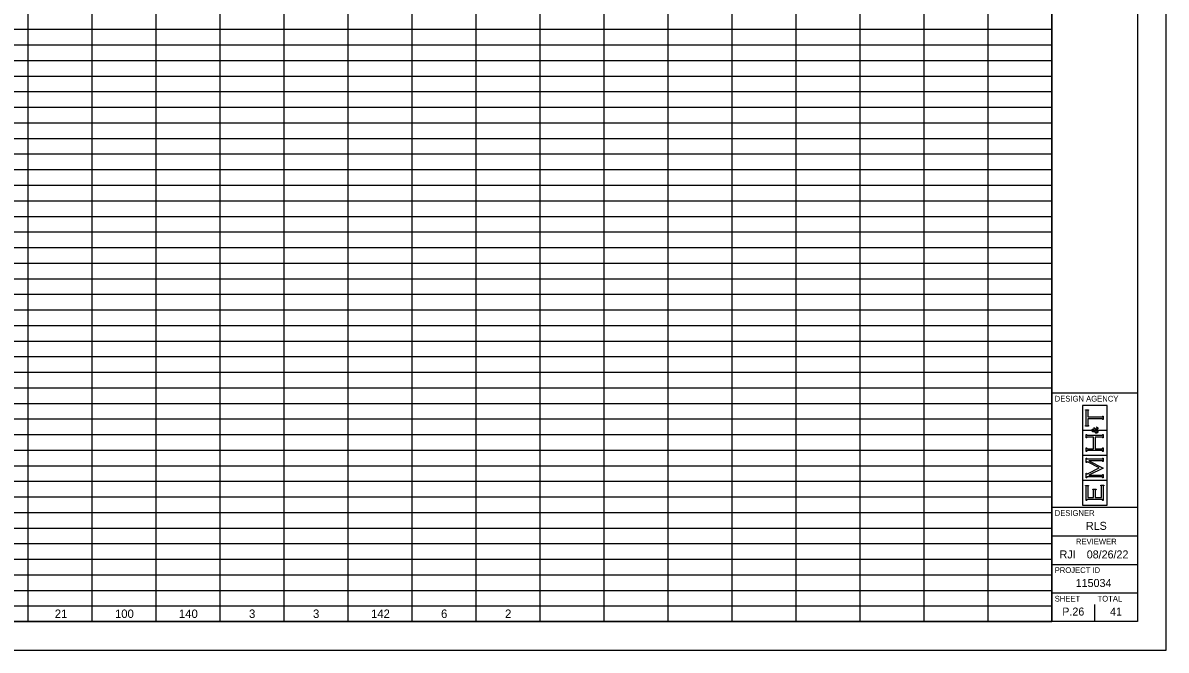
# Model space of a CAD drawing. Extents: x 0 to 34, y 0 to 22.
# Drawn here: x 14 to 34, y 0 to 10.98 of the extents above; entities that cross this region are included whole.
import ezdxf

# ---------------------------------------------------------------- set-up
doc = ezdxf.new("R2010")
doc.units = 0
for name, color, linetype in [('Default', 7, 'Continuous'), ('SH_Border', 7, 'Continuous'), ('SH_Cut_Line', 7, 'Continuous'), ('SH_Data', 7, 'Continuous')]:
    doc.layers.add(name, color=color, linetype=linetype)

msp = doc.modelspace()

# ---------------------------------------------------------------- linework, layer by layer
at = {"layer": 'Default'}
for p, q in [((14.082, 21.5), (14.082, 0.5)), ((15.202, 21.5), (15.202, 0.5)), ((16.322, 21.5), (16.322, 0.5)), ((17.442, 21.5), (17.442, 0.5)), ((18.562, 21.5), (18.562, 0.5)), ((19.681, 21.5), (19.681, 0.5)), ((20.801, 21.5), (20.801, 0.5)), ((21.921, 21.5), (21.921, 0.5)), ((23.041, 21.5), (23.041, 0.5)), ((24.161, 21.5), (24.161, 0.5)), ((25.281, 21.5), (25.281, 0.5)), ((26.401, 21.5), (26.401, 0.5)), ((27.521, 21.5), (27.521, 0.5)), ((28.64, 21.5), (28.64, 0.5)), ((29.76, 21.5), (29.76, 0.5)), ((30.88, 21.5), (30.88, 0.5)), ((32, 21.5), (32, 0.5)), ((1.5, 10.864), (32, 10.864)), ((1.5, 10.591), (32, 10.591)), ((1.5, 10.318), (32, 10.318)), ((1.5, 10.045), (32, 10.045)), ((1.5, 9.773), (32, 9.773)), ((1.5, 9.5), (32, 9.5)), ((1.5, 9.227), (32, 9.227)), ((1.5, 8.955), (32, 8.955)), ((1.5, 8.682), (32, 8.682)), ((1.5, 8.409), (32, 8.409)), ((1.5, 8.136), (32, 8.136)), ((1.5, 7.864), (32, 7.864)), ((1.5, 7.591), (32, 7.591)), ((1.5, 7.318), (32, 7.318)), ((1.5, 7.045), (32, 7.045)), ((1.5, 6.773), (32, 6.773)), ((1.5, 6.5), (32, 6.5)), ((1.5, 6.227), (32, 6.227)), ((1.5, 5.955), (32, 5.955)), ((1.5, 5.682), (32, 5.682)), ((1.5, 5.409), (32, 5.409)), ((1.5, 5.136), (32, 5.136)), ((1.5, 4.864), (32, 4.864)), ((1.5, 4.591), (32, 4.591)), ((1.5, 4.318), (32, 4.318)), ((1.5, 4.045), (32, 4.045)), ((1.5, 3.773), (32, 3.773)), ((1.5, 3.5), (32, 3.5)), ((1.5, 3.227), (32, 3.227)), ((1.5, 2.955), (32, 2.955)), ((1.5, 2.682), (32, 2.682)), ((1.5, 2.409), (32, 2.409)), ((1.5, 2.136), (32, 2.136)), ((1.5, 1.864), (32, 1.864)), ((1.5, 1.591), (32, 1.591)), ((1.5, 1.318), (32, 1.318)), ((1.5, 1.045), (32, 1.045)), ((1.5, 0.773), (32, 0.773)), ((1.5, 0.5), (32, 0.5))]:
    msp.add_line(p, q, dxfattribs=at)
at = {"layer": 'SH_Border'}
for p, q in [((32, 0.5), (32, 21.5)), ((32, 4.5), (33.5, 4.5)), ((32, 2.5), (33.5, 2.5)), ((32, 2), (33.5, 2)), ((32, 1.5), (33.5, 1.5)), ((32, 1), (33.5, 1))]:
    msp.add_line(p, q, dxfattribs=at)
msp.add_lwpolyline([(1.5, 21.5), (33.5, 21.5), (33.5, 0.5), (1.5, 0.5)], close=True, dxfattribs=at)
at = {"layer": 'SH_Cut_Line'}
msp.add_lwpolyline([(0, 0), (34, 0), (34, 22), (0, 22)], close=True, dxfattribs=at)
at = {"layer": 'SH_Data'}
for p, q in [((32.966, 4.28), (32.534, 4.28)), ((32.534, 4.28), (32.534, 3.848)), ((32.588, 4.199), (32.588, 4.206)), ((32.588, 4.206), (32.644, 4.206)), ((32.644, 4.206), (32.644, 4.199)), ((32.966, 3.848), (32.966, 4.28)), ((32.594, 4.198), (32.588, 4.199)), ((32.598, 4.196), (32.594, 4.198)), ((32.599, 4.194), (32.598, 4.196)), ((32.601, 4.191), (32.599, 4.194)), ((32.602, 4.187), (32.601, 4.191)), ((32.602, 4.181), (32.602, 4.187)), ((32.602, 3.947), (32.602, 4.181)), ((32.632, 4.191), (32.631, 4.187)), ((32.631, 4.187), (32.631, 4.181)), ((32.631, 4.181), (32.631, 4.081)), ((32.631, 4.081), (32.872, 4.081)), ((32.872, 4.047), (32.631, 4.047)), ((32.631, 4.047), (32.631, 3.947)), ((32.633, 4.194), (32.632, 4.191)), ((32.635, 4.196), (32.633, 4.194)), ((32.639, 4.198), (32.635, 4.196)), ((32.644, 4.199), (32.639, 4.198)), ((32.872, 4.081), (32.878, 4.081)), ((32.878, 4.047), (32.872, 4.047)), ((32.878, 4.081), (32.882, 4.082)), ((32.883, 4.046), (32.878, 4.047)), ((32.882, 4.082), (32.885, 4.084)), ((32.885, 4.044), (32.883, 4.046)), ((32.885, 4.084), (32.887, 4.085)), ((32.888, 4.042), (32.885, 4.044)), ((32.887, 4.085), (32.889, 4.089)), ((32.889, 4.039), (32.888, 4.042)), ((32.889, 4.089), (32.891, 4.095)), ((32.891, 4.033), (32.889, 4.039)), ((32.891, 4.095), (32.898, 4.095)), ((32.898, 4.033), (32.891, 4.033)), ((32.898, 4.095), (32.898, 4.033)), ((32.534, 3.848), (32.693, 3.848)), ((32.693, 3.842), (32.534, 3.842)), ((32.534, 3.842), (32.534, 3.41)), ((32.588, 3.928), (32.594, 3.93)), ((32.588, 3.921), (32.588, 3.928)), ((32.644, 3.921), (32.588, 3.921)), ((32.594, 3.93), (32.598, 3.932)), ((32.598, 3.932), (32.599, 3.934)), ((32.599, 3.934), (32.601, 3.937)), ((32.601, 3.937), (32.602, 3.941)), ((32.602, 3.941), (32.602, 3.947)), ((32.631, 3.947), (32.631, 3.941)), ((32.631, 3.941), (32.632, 3.937)), ((32.632, 3.937), (32.633, 3.934)), ((32.633, 3.934), (32.635, 3.932)), ((32.635, 3.932), (32.639, 3.93)), ((32.639, 3.93), (32.644, 3.928)), ((32.644, 3.928), (32.644, 3.921)), ((32.693, 3.848), (32.693, 3.842)), ((32.701, 3.852), (32.703, 3.857)), ((32.701, 3.846), (32.701, 3.852)), ((32.701, 3.84), (32.701, 3.846)), ((32.703, 3.835), (32.701, 3.84)), ((32.703, 3.857), (32.706, 3.861)), ((32.706, 3.83), (32.703, 3.835)), ((32.706, 3.861), (32.71, 3.864)), ((32.707, 3.852), (32.706, 3.849)), ((32.706, 3.849), (32.706, 3.846)), ((32.706, 3.846), (32.706, 3.842)), ((32.706, 3.842), (32.708, 3.839)), ((32.71, 3.824), (32.706, 3.83)), ((32.71, 3.854), (32.707, 3.852)), ((32.708, 3.839), (32.711, 3.837)), ((32.71, 3.864), (32.714, 3.866)), ((32.712, 3.856), (32.71, 3.854)), ((32.717, 3.821), (32.71, 3.824)), ((32.711, 3.837), (32.714, 3.835)), ((32.715, 3.857), (32.712, 3.856)), ((32.714, 3.866), (32.719, 3.866)), ((32.714, 3.835), (32.716, 3.834)), ((32.718, 3.857), (32.715, 3.857)), ((32.716, 3.834), (32.719, 3.834)), ((32.725, 3.821), (32.717, 3.821)), ((32.723, 3.857), (32.718, 3.857)), ((32.719, 3.866), (32.724, 3.866)), ((32.719, 3.834), (32.722, 3.834)), ((32.722, 3.834), (32.724, 3.834)), ((32.727, 3.856), (32.723, 3.857)), ((32.724, 3.866), (32.728, 3.864)), ((32.724, 3.834), (32.727, 3.835)), ((32.728, 3.821), (32.725, 3.821)), ((32.73, 3.853), (32.727, 3.856)), ((32.727, 3.835), (32.73, 3.836)), ((32.728, 3.864), (32.732, 3.861)), ((32.731, 3.822), (32.728, 3.821)), ((32.734, 3.85), (32.73, 3.853)), ((32.73, 3.836), (32.734, 3.837)), ((32.734, 3.822), (32.731, 3.822)), ((32.732, 3.861), (32.736, 3.857)), ((32.737, 3.845), (32.734, 3.85)), ((32.734, 3.837), (32.74, 3.839)), ((32.737, 3.823), (32.734, 3.822)), ((32.736, 3.857), (32.74, 3.851)), ((32.74, 3.839), (32.737, 3.845)), ((32.741, 3.825), (32.737, 3.823)), ((32.738, 3.867), (32.738, 3.898)), ((32.738, 3.898), (32.741, 3.898)), ((32.741, 3.867), (32.738, 3.867)), ((32.74, 3.851), (32.745, 3.842)), ((32.741, 3.898), (32.741, 3.894)), ((32.741, 3.894), (32.742, 3.891)), ((32.742, 3.871), (32.741, 3.869)), ((32.741, 3.869), (32.741, 3.867)), ((32.746, 3.827), (32.741, 3.825)), ((32.742, 3.891), (32.744, 3.889)), ((32.743, 3.872), (32.742, 3.871)), ((32.745, 3.873), (32.743, 3.872)), ((32.744, 3.889), (32.745, 3.887)), ((32.745, 3.887), (32.75, 3.883)), ((32.747, 3.874), (32.745, 3.873)), ((32.745, 3.842), (32.755, 3.848)), ((32.753, 3.815), (32.746, 3.827)), ((32.749, 3.874), (32.747, 3.874)), ((32.756, 3.874), (32.749, 3.874)), ((32.75, 3.883), (32.757, 3.879)), ((32.757, 3.832), (32.751, 3.829)), ((32.751, 3.829), (32.755, 3.824)), ((32.759, 3.808), (32.753, 3.815)), ((32.755, 3.848), (32.765, 3.855)), ((32.755, 3.824), (32.758, 3.819)), ((32.764, 3.87), (32.756, 3.874)), ((32.757, 3.879), (32.765, 3.875)), ((32.762, 3.835), (32.757, 3.832)), ((32.758, 3.819), (32.762, 3.817)), ((32.765, 3.803), (32.759, 3.808)), ((32.766, 3.838), (32.762, 3.835)), ((32.762, 3.817), (32.766, 3.814)), ((32.775, 3.861), (32.764, 3.87)), ((32.765, 3.875), (32.772, 3.87)), ((32.765, 3.855), (32.775, 3.861)), ((32.77, 3.799), (32.765, 3.803)), ((32.77, 3.84), (32.766, 3.838)), ((32.766, 3.814), (32.771, 3.812)), ((32.776, 3.845), (32.77, 3.84)), ((32.771, 3.812), (32.775, 3.812)), ((32.772, 3.87), (32.779, 3.865)), ((32.775, 3.812), (32.78, 3.812)), ((32.785, 3.851), (32.776, 3.845)), ((32.779, 3.865), (32.784, 3.869)), ((32.78, 3.812), (32.785, 3.814)), ((32.781, 3.9), (32.783, 3.902)), ((32.785, 3.899), (32.781, 3.9)), ((32.783, 3.902), (32.79, 3.901)), ((32.784, 3.869), (32.787, 3.873)), ((32.788, 3.897), (32.785, 3.899)), ((32.789, 3.846), (32.785, 3.851)), ((32.785, 3.814), (32.789, 3.817)), ((32.787, 3.873), (32.789, 3.876)), ((32.789, 3.895), (32.788, 3.897)), ((32.791, 3.892), (32.789, 3.895)), ((32.789, 3.876), (32.791, 3.88)), ((32.794, 3.859), (32.789, 3.855)), ((32.789, 3.855), (32.795, 3.849)), ((32.792, 3.842), (32.789, 3.846)), ((32.789, 3.817), (32.793, 3.821)), ((32.79, 3.901), (32.795, 3.898)), ((32.792, 3.89), (32.791, 3.892)), ((32.791, 3.88), (32.792, 3.883)), ((32.792, 3.886), (32.792, 3.89)), ((32.792, 3.883), (32.792, 3.886)), ((32.793, 3.839), (32.792, 3.842)), ((32.794, 3.837), (32.793, 3.839)), ((32.793, 3.821), (32.795, 3.825)), ((32.797, 3.804), (32.793, 3.8)), ((32.798, 3.864), (32.794, 3.859)), ((32.795, 3.834), (32.794, 3.837)), ((32.795, 3.898), (32.799, 3.894)), ((32.795, 3.849), (32.798, 3.843)), ((32.795, 3.831), (32.795, 3.834)), ((32.795, 3.825), (32.795, 3.831)), ((32.801, 3.809), (32.797, 3.804)), ((32.8, 3.868), (32.798, 3.864)), ((32.798, 3.843), (32.8, 3.839)), ((32.799, 3.894), (32.802, 3.89)), ((32.802, 3.872), (32.8, 3.868)), ((32.8, 3.839), (32.802, 3.834)), ((32.803, 3.815), (32.801, 3.809)), ((32.802, 3.89), (32.803, 3.885)), ((32.803, 3.876), (32.802, 3.872)), ((32.802, 3.834), (32.803, 3.829)), ((32.803, 3.885), (32.803, 3.88)), ((32.803, 3.88), (32.803, 3.876)), ((32.807, 3.842), (32.803, 3.848)), ((32.803, 3.848), (32.966, 3.848)), ((32.803, 3.829), (32.803, 3.823)), ((32.803, 3.823), (32.803, 3.815)), ((32.966, 3.842), (32.807, 3.842)), ((32.966, 3.41), (32.966, 3.842)), ((32.602, 3.714), (32.602, 3.776)), ((32.602, 3.776), (32.609, 3.776)), ((32.609, 3.714), (32.602, 3.714)), ((32.609, 3.776), (32.611, 3.77)), ((32.61, 3.72), (32.609, 3.714)), ((32.612, 3.723), (32.61, 3.72)), ((32.611, 3.77), (32.612, 3.766)), ((32.612, 3.766), (32.615, 3.765)), ((32.615, 3.725), (32.612, 3.723)), ((32.615, 3.765), (32.617, 3.763)), ((32.617, 3.727), (32.615, 3.725)), ((32.617, 3.763), (32.622, 3.762)), ((32.622, 3.728), (32.617, 3.727)), ((32.622, 3.762), (32.628, 3.762)), ((32.628, 3.728), (32.622, 3.728)), ((32.628, 3.762), (32.872, 3.762)), ((32.732, 3.728), (32.628, 3.728)), ((32.732, 3.525), (32.732, 3.728)), ((32.872, 3.728), (32.76, 3.728)), ((32.76, 3.728), (32.76, 3.525)), ((32.776, 3.797), (32.77, 3.799)), ((32.782, 3.797), (32.776, 3.797)), ((32.788, 3.797), (32.782, 3.797)), ((32.793, 3.8), (32.788, 3.797)), ((32.872, 3.762), (32.878, 3.762)), ((32.878, 3.728), (32.872, 3.728)), ((32.878, 3.762), (32.882, 3.763)), ((32.883, 3.727), (32.878, 3.728)), ((32.882, 3.763), (32.885, 3.765)), ((32.885, 3.725), (32.883, 3.727)), ((32.885, 3.765), (32.887, 3.766)), ((32.888, 3.723), (32.885, 3.725)), ((32.887, 3.766), (32.889, 3.77)), ((32.889, 3.72), (32.888, 3.723)), ((32.889, 3.77), (32.891, 3.776)), ((32.891, 3.714), (32.889, 3.72)), ((32.891, 3.776), (32.898, 3.776)), ((32.898, 3.714), (32.891, 3.714)), ((32.898, 3.776), (32.898, 3.714)), ((32.534, 3.41), (32.966, 3.41)), ((32.966, 3.405), (32.534, 3.405)), ((32.534, 3.405), (32.534, 2.973)), ((32.602, 3.477), (32.602, 3.538)), ((32.602, 3.538), (32.609, 3.538)), ((32.609, 3.477), (32.602, 3.477)), ((32.609, 3.538), (32.611, 3.533)), ((32.61, 3.482), (32.609, 3.477)), ((32.612, 3.486), (32.61, 3.482)), ((32.611, 3.533), (32.612, 3.529)), ((32.612, 3.529), (32.615, 3.527)), ((32.615, 3.488), (32.612, 3.486)), ((32.615, 3.527), (32.617, 3.526)), ((32.617, 3.49), (32.615, 3.488)), ((32.617, 3.526), (32.622, 3.525)), ((32.622, 3.491), (32.617, 3.49)), ((32.622, 3.525), (32.628, 3.525)), ((32.628, 3.491), (32.622, 3.491)), ((32.628, 3.525), (32.732, 3.525)), ((32.872, 3.491), (32.628, 3.491)), ((32.75, 3.5), (32.75, 3.5)), ((32.76, 3.525), (32.872, 3.525)), ((32.872, 3.525), (32.878, 3.525)), ((32.878, 3.491), (32.872, 3.491)), ((32.878, 3.525), (32.883, 3.525)), ((32.883, 3.49), (32.878, 3.491)), ((32.883, 3.525), (32.885, 3.527)), ((32.885, 3.488), (32.883, 3.49)), ((32.885, 3.527), (32.888, 3.529)), ((32.887, 3.486), (32.885, 3.488)), ((32.888, 3.529), (32.889, 3.533)), ((32.889, 3.482), (32.887, 3.486)), ((32.889, 3.533), (32.891, 3.538)), ((32.891, 3.477), (32.889, 3.482)), ((32.891, 3.538), (32.898, 3.538)), ((32.898, 3.477), (32.891, 3.477)), ((32.898, 3.538), (32.898, 3.477)), ((32.966, 2.973), (32.966, 3.405)), ((32.602, 3.283), (32.602, 3.36)), ((32.602, 3.36), (32.609, 3.36)), ((32.609, 3.283), (32.602, 3.283)), ((32.609, 3.36), (32.611, 3.354)), ((32.612, 3.29), (32.609, 3.283)), ((32.611, 3.354), (32.612, 3.351)), ((32.612, 3.351), (32.615, 3.349)), ((32.615, 3.293), (32.612, 3.29)), ((32.615, 3.349), (32.617, 3.347)), ((32.618, 3.293), (32.615, 3.293)), ((32.617, 3.347), (32.622, 3.346)), ((32.621, 3.293), (32.618, 3.293)), ((32.626, 3.292), (32.621, 3.293)), ((32.622, 3.346), (32.628, 3.346)), ((32.633, 3.288), (32.626, 3.292)), ((32.628, 3.346), (32.872, 3.346)), ((32.831, 3.189), (32.633, 3.288)), ((32.872, 3.312), (32.649, 3.312)), ((32.649, 3.312), (32.898, 3.186)), ((32.872, 3.346), (32.878, 3.346)), ((32.878, 3.312), (32.872, 3.312)), ((32.878, 3.346), (32.882, 3.347)), ((32.883, 3.311), (32.878, 3.312)), ((32.882, 3.347), (32.885, 3.349)), ((32.885, 3.31), (32.883, 3.311)), ((32.885, 3.349), (32.887, 3.351)), ((32.887, 3.308), (32.885, 3.31)), ((32.887, 3.351), (32.889, 3.354)), ((32.889, 3.304), (32.887, 3.308)), ((32.889, 3.354), (32.891, 3.36)), ((32.891, 3.298), (32.889, 3.304)), ((32.891, 3.36), (32.898, 3.36)), ((32.898, 3.298), (32.891, 3.298)), ((32.898, 3.36), (32.898, 3.298)), ((32.602, 3.017), (32.602, 3.094)), ((32.602, 3.094), (32.609, 3.094)), ((32.609, 3.017), (32.602, 3.017)), ((32.609, 3.094), (32.612, 3.087)), ((32.61, 3.023), (32.609, 3.017)), ((32.612, 3.026), (32.61, 3.023)), ((32.612, 3.087), (32.615, 3.083)), ((32.615, 3.028), (32.612, 3.026)), ((32.615, 3.083), (32.618, 3.083)), ((32.617, 3.03), (32.615, 3.028)), ((32.622, 3.031), (32.617, 3.03)), ((32.618, 3.083), (32.62, 3.083)), ((32.62, 3.083), (32.625, 3.086)), ((32.628, 3.031), (32.622, 3.031)), ((32.625, 3.086), (32.635, 3.09)), ((32.872, 3.031), (32.628, 3.031)), ((32.635, 3.09), (32.831, 3.189)), ((32.898, 3.186), (32.649, 3.062)), ((32.649, 3.062), (32.872, 3.062)), ((32.872, 3.062), (32.878, 3.062)), ((32.878, 3.031), (32.872, 3.031)), ((32.878, 3.062), (32.882, 3.063)), ((32.883, 3.03), (32.878, 3.031)), ((32.882, 3.063), (32.885, 3.065)), ((32.885, 3.028), (32.883, 3.03)), ((32.885, 3.065), (32.887, 3.067)), ((32.887, 3.026), (32.885, 3.028)), ((32.887, 3.067), (32.889, 3.07)), ((32.889, 3.023), (32.887, 3.026)), ((32.889, 3.07), (32.891, 3.076)), ((32.891, 3.017), (32.889, 3.023)), ((32.891, 3.076), (32.898, 3.076)), ((32.898, 3.017), (32.891, 3.017)), ((32.898, 3.076), (32.898, 3.017)), ((32.534, 2.973), (32.966, 2.973)), ((32.966, 2.967), (32.534, 2.967)), ((32.534, 2.967), (32.534, 2.535)), ((32.588, 2.874), (32.588, 2.881)), ((32.588, 2.881), (32.644, 2.881)), ((32.594, 2.873), (32.588, 2.874)), ((32.598, 2.871), (32.594, 2.873)), ((32.599, 2.868), (32.598, 2.871)), ((32.601, 2.866), (32.599, 2.868)), ((32.602, 2.862), (32.601, 2.866)), ((32.602, 2.856), (32.602, 2.862)), ((32.602, 2.621), (32.602, 2.856)), ((32.632, 2.866), (32.631, 2.862)), ((32.631, 2.862), (32.631, 2.856)), ((32.631, 2.856), (32.631, 2.669)), ((32.633, 2.868), (32.632, 2.866)), ((32.635, 2.871), (32.633, 2.868)), ((32.639, 2.873), (32.635, 2.871)), ((32.644, 2.874), (32.639, 2.873)), ((32.644, 2.881), (32.644, 2.874)), ((32.718, 2.81), (32.718, 2.816)), ((32.718, 2.816), (32.774, 2.816)), ((32.723, 2.808), (32.718, 2.81)), ((32.727, 2.806), (32.723, 2.808)), ((32.729, 2.804), (32.727, 2.806)), ((32.731, 2.801), (32.729, 2.804)), ((32.732, 2.797), (32.731, 2.801)), ((32.761, 2.801), (32.76, 2.797)), ((32.763, 2.804), (32.761, 2.801)), ((32.765, 2.806), (32.763, 2.804)), ((32.768, 2.808), (32.765, 2.806)), ((32.774, 2.81), (32.768, 2.808)), ((32.774, 2.816), (32.774, 2.81)), ((32.855, 2.877), (32.855, 2.884)), ((32.855, 2.884), (32.912, 2.884)), ((32.861, 2.876), (32.855, 2.877)), ((32.865, 2.874), (32.861, 2.876)), ((32.867, 2.872), (32.865, 2.874)), ((32.868, 2.869), (32.867, 2.872)), ((32.869, 2.865), (32.868, 2.869)), ((32.869, 2.859), (32.869, 2.865)), ((32.869, 2.669), (32.869, 2.859)), ((32.899, 2.869), (32.898, 2.865)), ((32.898, 2.865), (32.898, 2.858)), ((32.898, 2.858), (32.898, 2.621)), ((32.901, 2.871), (32.899, 2.869)), ((32.903, 2.874), (32.901, 2.871)), ((32.906, 2.876), (32.903, 2.874)), ((32.912, 2.877), (32.906, 2.876)), ((32.912, 2.884), (32.912, 2.877)), ((32.966, 2.535), (32.966, 2.967)), ((32.609, 2.621), (32.602, 2.621)), ((32.611, 2.626), (32.609, 2.621)), ((32.612, 2.63), (32.611, 2.626)), ((32.615, 2.632), (32.612, 2.63)), ((32.617, 2.634), (32.615, 2.632)), ((32.622, 2.635), (32.617, 2.634)), ((32.628, 2.635), (32.622, 2.635)), ((32.872, 2.635), (32.628, 2.635)), ((32.631, 2.669), (32.732, 2.669)), ((32.732, 2.791), (32.732, 2.797)), ((32.732, 2.669), (32.732, 2.791)), ((32.76, 2.797), (32.76, 2.791)), ((32.76, 2.791), (32.76, 2.669)), ((32.76, 2.669), (32.869, 2.669)), ((32.878, 2.635), (32.872, 2.635)), ((32.883, 2.634), (32.878, 2.635)), ((32.885, 2.632), (32.883, 2.634)), ((32.887, 2.63), (32.885, 2.632)), ((32.889, 2.627), (32.887, 2.63)), ((32.891, 2.621), (32.889, 2.627)), ((32.898, 2.621), (32.891, 2.621)), ((32.534, 2.535), (32.966, 2.535)), ((32.375, 0.675), (32.375, 0.675)), ((32.75, 0.5), (32.75, 0.8))]:
    msp.add_line(p, q, dxfattribs=at)

# ---------------------------------------------------------------- texts
at = {"layer": 'Default'}
for s, height, p in [('21', 0.1476, (14.554, 0.563)), ('100', 0.1476, (15.608, 0.563)), ('140', 0.1476, (16.727, 0.563)), ('3', 0.148, (17.953, 0.563)), ('3', 0.148, (19.073, 0.563)), ('142', 0.1476, (20.088, 0.563)), ('6', 0.148, (21.313, 0.563)), ('2', 0.148, (22.433, 0.563))]:
    msp.add_text(s, height=height, dxfattribs=at).set_placement(p)
at = {"layer": 'SH_Data'}
for s, height, p in [('DESIGN AGENCY', 0.1, (32.05, 4.35)), ('DESIGNER', 0.1, (32.05, 2.35)), ('RLS', 0.14, (32.597, 2.105)), ('REVIEWER', 0.1, (32.422, 1.85)), ('RJI', 0.14, (32.136, 1.605)), ('08/26/22', 0.14, (32.611, 1.605)), ('PROJECT ID', 0.1, (32.05, 1.35)), ('115034', 0.14, (32.418, 1.105)), ('SHEET', 0.1, (32.05, 0.85)), ('TOTAL', 0.1, (32.8, 0.85)), ('P.26', 0.14, (32.183, 0.605)), ('41', 0.14, (33.019, 0.605))]:
    msp.add_text(s, height=height, dxfattribs=at).set_placement(p)

doc.saveas('drawing.dxf')
